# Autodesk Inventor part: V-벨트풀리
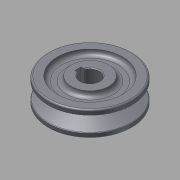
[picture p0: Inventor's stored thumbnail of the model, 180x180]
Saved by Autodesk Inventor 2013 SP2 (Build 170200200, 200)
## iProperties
Created: 2015-12
Part Number: V-벨트풀리
Material: 강철, 연강
Document SubType Name: Modeling
Designer: mdu
Density: 7.86 g/cm^3
CustomPartVersion: 1
Author: mdu
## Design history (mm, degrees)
sketch "주 스케치"
  geometry: L1 (0, 16)-(27, 16); L2 (27, 16)-(27, 12.861); L3 (27, 12.861)-(16, 9.498); L4 (16, 9.498)-(16, 6.502); L5 (16, 6.502)-(27, 3.139); L6 (27, 3.139)-(27, 0); L7 (27, 0)-(0, 0); L8 (25, 12.25)-(25, 3.75); L9 (16, 8)-(25, 8); L10 (27, 12.861)-(27, 3.139); L11 (0, -3)-(0, 18) reference; L12 (0, 0)-(0, 16)
  constraints: 22 end point, 5 perpendicular, 2 collinear, 2 midpoint, 2 point on line, 1 parallel
  dimensions: "d0" = 8.5 distance of L8.start L8.end (= da_Bw); "d1" = 34 deg angle of L3 L5 (= da_Alfa); "d2" = 2 distance between parallel lines of L2 L8 (= da_c); "d6" = 16 distance between parallel lines of L7 L1 (computed from d5, da_ng, da_Sg); "d21" = 50 diameter of L8 L11 (= da_Dw); "d25" = 11 distance between parallel lines of L4 L10 (= da_Hd); "d27" = 8 distance between parallel lines of L7 L9 (= da_Se)
node "벨트 평면"
revolve "본체" stored, may be unused: angle "d7" = 90 deg
revolve "그루브" stored, may be unused: angle "d15" = 90 deg
feature "허브 키홈"
fillet "모깎기3" dims "d28" = 0.5, "d29" = 1, "d30" = 1
sketch "스케치2"
  geometry: C1 r 12 at (0, 0); C2 r 21 at (0, 0); 1 further point
  constraints: 2 centre point, 2 coincident
  dimensions: "d31" = 24 diameter of C1; "d32" = 42 diameter of C2
extrude "돌출1" cut sketch "스케치2" distance "d33" = 3; taper "d34" = 0 deg
fillet "모깎기4" dims "d35" = 3
node "작업 평면2"
chamfer "모따기1" distance "d36" = 0.5; stored, may be unused: second distance "d37" = 2, angle "d38" = 45 deg
body "Solid1"
pattern_linear "그루브 패턴" dims "d18" = 12 (= da_Sg)
mirror "대칭1"
other parameters: "d5" = 8 (= da_Se), "da_Bw" = 8.5 [user parameter; used in 1 equation term], "da_Alfa" = 34 deg [user parameter; used in 1 equation term], "da_c" = 2 [user parameter; used in 1 equation term], "da_Dw" = 50 [user parameter; used in 1 equation term], "da_Hd" = 11 [user parameter; used in 1 equation term], "da_Se" = 8 [user parameter; used in 2 equation terms], "da_Sg" = 12 [user parameter; used in 2 equation terms], "da_r1" = 0 [user parameter], "da_r2" = 0 [user parameter], "d24" = 0, "d26" = 0
